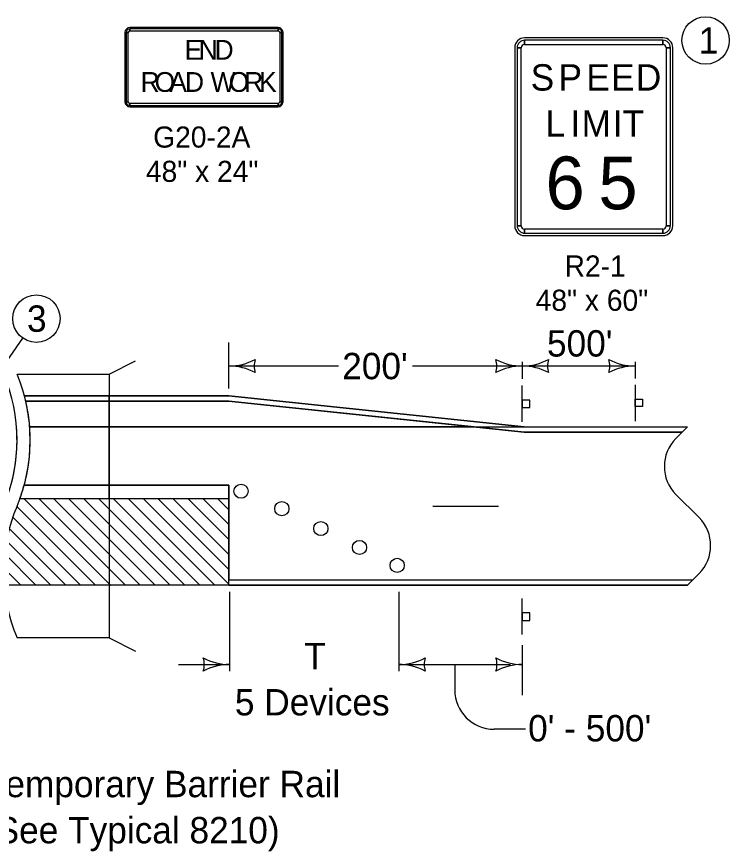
# Model space of a CAD drawing. Extents: x 10133 to 2270741, y 5363 to 1733450.
# Drawn here: x 30695 to 31236, y 11491 to 12124 of the extents above; entities that cross this region are included whole.
import ezdxf

# ---------------------------------------------------------------- set-up
doc = ezdxf.new("R2010")
doc.units = 0
for name, color, linetype in [('dsnNonPlotable', 7, 'Continuous'), ('dsnShtPlotShapeBatchPrint', 7, 'Continuous'), ('dsnStdBorder', 7, 'Continuous'), ('dsnStdLabel', 7, 'Continuous'), ('Level 12', 7, 'Continuous'), ('Level 2', 7, 'Continuous')]:
    doc.layers.add(name, color=color, linetype=linetype)

msp = doc.modelspace()

# ---------------------------------------------------------------- linework, layer by layer
at = {"layer": 'dsnNonPlotable'}
for p, q in [((30765.21, 11852.62), (30785.21, 11862.62)), ((30695.21, 11852.62), (30765.21, 11852.62)), ((30701.82, 11832.12), (30855.98, 11832.12)), ((30855.98, 11832.12), (31080.18, 11808.62)), ((30704.83, 11812.62), (31080.2, 11812.62)), ((31204.03, 11812.62), (31195.24, 11803.83)), ((30855.98, 11768.35), (30700.62, 11768.35)), ((30855.98, 11758.35), (30855.98, 11768.35)), ((31195.24, 11761.4), (31212.81, 11743.83)), ((30697.45, 11758.35), (30855.98, 11758.35)), ((31212.81, 11701.4), (31204.03, 11692.62)), ((30765.21, 11652.62), (30785.21, 11642.62))]:
    msp.add_line(p, q, dxfattribs=at)
for points in [[(30765.21, 11852.62), (30765.21, 11652.62), (30695.21, 11652.62)], [(31080.18, 11808.62), (31200.03, 11808.62)], [(30713.68, 11768.35), (30700.62, 11768.35)], [(30697.45, 11758.35), (30710.51, 11758.35)], [(31010.64, 11752.62), (31060.64, 11752.62)], [(30855.98, 11696.62), (31208.03, 11696.62)]]:
    msp.add_lwpolyline(points, dxfattribs=at)
for centre, radius, start, end in [((30565.21, 11802.62), 130, 337.38013, 22.61986), ((30575.21, 11802.62), 130, 337.38013, 22.61986), ((31216.46, 11782.62), 30, 135, 225), ((30815.21, 11702.62), 130, 157.38013, 202.61986), ((31191.6, 11722.62), 30, 315, 45)]:
    msp.add_arc(centre, radius, start, end, dxfattribs=at)
at = {"layer": 'dsnShtPlotShapeBatchPrint'}
for centre in [(31217.76, 12105.69), (30709.93, 11894.73)]:
    msp.add_circle(centre, 18, dxfattribs=at)
at = {"layer": 'dsnStdBorder'}
for p, q in [((30893.34, 12115.42), (30780.84, 12115.42)), ((30780.84, 12112.92), (30780.84, 12114.49)), ((30893.34, 12114.49), (30893.34, 12112.92)), ((30777.09, 12111.67), (30777.09, 12059.17)), ((30778.03, 12111.67), (30779.59, 12111.67)), ((30894.59, 12111.67), (30896.15, 12111.67)), ((30897.09, 12059.17), (30897.09, 12111.67)), ((31185.39, 12107.65), (31080.39, 12107.65)), ((31080.39, 12102.65), (31080.39, 12105.78)), ((31185.39, 12105.78), (31185.39, 12102.65)), ((31072.89, 12100.15), (31072.89, 11965.15)), ((31074.77, 12100.15), (31077.89, 12100.15)), ((31187.89, 12100.15), (31191.02, 12100.15)), ((31192.89, 11965.15), (31192.89, 12100.15)), ((30779.59, 12059.17), (30778.03, 12059.17)), ((30780.84, 12056.36), (30780.84, 12057.92)), ((30893.34, 12057.92), (30893.34, 12056.36)), ((30896.15, 12059.17), (30894.59, 12059.17)), ((30780.84, 12055.42), (30893.34, 12055.42)), ((31077.89, 11965.15), (31074.77, 11965.15)), ((31080.39, 11959.53), (31080.39, 11962.65)), ((31185.39, 11962.65), (31185.39, 11959.53)), ((31191.02, 11965.15), (31187.89, 11965.15)), ((31080.39, 11957.65), (31185.39, 11957.65)), ((31078.59, 11816.53), (31078.59, 11844.03)), ((31164.24, 11844.5), (31164.24, 11817)), ((30855.98, 11832.12), (31080.18, 11808.62)), ((31080.18, 11808.62), (31200.03, 11808.62)), ((30713.68, 11768.35), (30700.62, 11768.35)), ((30765.21, 11768.35), (30713.68, 11768.35)), ((30855.98, 11768.35), (30765.21, 11768.35)), ((30765.21, 11768.35), (30765.21, 11758.35)), ((30765.21, 11758.35), (30765.21, 11768.35)), ((30855.98, 11758.35), (30855.98, 11768.35)), ((30697.45, 11758.35), (30710.51, 11758.35)), ((30700.38, 11758.35), (30766.11, 11692.62)), ((30710.51, 11758.35), (30765.21, 11758.35)), ((30711.69, 11758.35), (30777.42, 11692.62)), ((30723, 11758.35), (30788.74, 11692.62)), ((30734.32, 11758.35), (30800.05, 11692.62)), ((30745.63, 11758.35), (30811.37, 11692.62)), ((30756.94, 11758.35), (30822.68, 11692.62)), ((30765.21, 11758.35), (30855.98, 11758.35)), ((30768.26, 11758.35), (30833.99, 11692.62)), ((30779.57, 11758.35), (30845.31, 11692.62)), ((30790.89, 11758.35), (30855.98, 11693.26)), ((30802.2, 11758.35), (30855.98, 11704.58)), ((30813.51, 11758.35), (30855.98, 11715.89)), ((30824.83, 11758.35), (30855.98, 11727.2)), ((30836.14, 11758.35), (30855.98, 11738.52)), ((30847.45, 11758.35), (30855.98, 11749.83)), ((30855.98, 11692.62), (30855.98, 11758.35)), ((30695.09, 11752.32), (30754.8, 11692.62)), ((30692.01, 11744.09), (30743.48, 11692.62)), ((30689.41, 11735.38), (30732.17, 11692.62)), ((30687.36, 11726.12), (30720.86, 11692.62)), ((30685.93, 11716.23), (30709.54, 11692.62)), ((30685.25, 11705.6), (30698.23, 11692.62)), ((30766.11, 11692.62), (30765.21, 11693.51)), ((30765.21, 11693.51), (30765.21, 11692.62)), ((30765.21, 11692.62), (30766.11, 11692.62)), ((31078.59, 11655.08), (31078.59, 11682.58))]:
    msp.add_line(p, q, dxfattribs=at)
for points in [[(30893.34, 12114.49), (30780.84, 12114.49), (30780.84, 12112.92), (30893.34, 12112.92), (30893.34, 12114.49)], [(30778.03, 12111.67), (30778.03, 12059.17), (30779.59, 12059.17), (30779.59, 12111.67), (30778.03, 12111.67)], [(30896.15, 12059.17), (30896.15, 12111.67), (30894.59, 12111.67), (30894.59, 12059.17), (30896.15, 12059.17)], [(31185.39, 12105.78), (31080.39, 12105.78), (31080.39, 12102.65), (31185.39, 12102.65), (31185.39, 12105.78)], [(31074.77, 12100.15), (31074.77, 11965.15), (31077.89, 11965.15), (31077.89, 12100.15), (31074.77, 12100.15)], [(31191.02, 11965.15), (31191.02, 12100.15), (31187.89, 12100.15), (31187.89, 11965.15), (31191.02, 11965.15)], [(30780.84, 12056.36), (30893.34, 12056.36), (30893.34, 12057.92), (30780.84, 12057.92), (30780.84, 12056.36)], [(31080.39, 11959.53), (31185.39, 11959.53), (31185.39, 11962.65), (31080.39, 11962.65), (31080.39, 11959.53)], [(31078.68, 11832.98), (31078.68, 11827.35), (31084.31, 11827.35), (31084.31, 11832.98)], [(31164.34, 11828.05), (31164.34, 11833.68), (31169.96, 11833.68), (31169.96, 11828.05)], [(31078.68, 11671.53), (31078.68, 11665.9), (31084.31, 11665.9), (31084.31, 11671.53)]]:
    msp.add_lwpolyline(points, close=True, dxfattribs=at)
for centre in [(30865.2, 11763.82), (30865.2, 11763.82), (30896.16, 11750.6), (30896.16, 11750.6), (30925.78, 11735.5), (30925.78, 11735.5), (30955.11, 11721.19), (30955.11, 11721.19), (30983.7, 11707.58), (30983.7, 11707.58)]:
    msp.add_circle(centre, 5.37, dxfattribs=at)
for centre, radius, start, end in [((30780.84, 12111.67), 3.75, 90.00021, 179.99985), ((30780.84, 12111.67), 2.81, 90.00021, 179.99985), ((30893.34, 12111.67), 3.75, 0, 90.00021), ((30893.34, 12111.67), 2.81, 0, 90.00021), ((30780.84, 12111.67), 1.25, 90.00021, 179.99985), ((30893.34, 12111.67), 1.25, 0, 90.00021), ((31080.39, 12100.15), 7.5, 90.00021, 179.99985), ((31080.39, 12100.15), 5.62, 90.00021, 179.99985), ((31080.39, 12100.15), 2.5, 90.00021, 179.99985), ((31185.39, 12100.15), 7.5, 0, 90.00021), ((31185.39, 12100.15), 5.62, 0, 90.00021), ((31185.39, 12100.15), 2.5, 0, 90.00021), ((30780.84, 12059.17), 3.75, 179.99985, 270.00006), ((30780.84, 12059.17), 2.81, 179.99985, 270.00006), ((30780.84, 12059.17), 1.25, 179.99985, 270.00006), ((30893.34, 12059.17), 3.75, 270.00006, 0.00027), ((30893.34, 12059.17), 2.81, 270.00006, 0.00027), ((30893.34, 12059.17), 1.25, 270.00006, 0.00027), ((31080.39, 11965.15), 7.5, 179.99985, 270.00006), ((31080.39, 11965.15), 5.62, 179.99985, 270.00006), ((31080.39, 11965.15), 2.5, 179.99985, 270.00006), ((31185.39, 11965.15), 7.5, 270.00006, 0.00027), ((31185.39, 11965.15), 5.62, 270.00006, 0.00027), ((31185.39, 11965.15), 2.5, 270.00006, 0.00027), ((30855.98, 11901.26), 42.5, 270, 298.07249), ((30891.61, 11858.76), 16.42, 162.26665, 197.73335), ((31042.95, 11858.76), 16.42, 342.26665, 17.73335), ((31078.59, 11901.26), 42.5, 241.92751, 270), ((31078.59, 11901.26), 42.5, 270, 298.07249), ((31114.22, 11858.76), 16.42, 162.26665, 197.73335), ((31128.6, 11858.76), 16.42, 342.26665, 17.73335), ((31164.24, 11901.26), 42.5, 241.92751, 270), ((30855.98, 11816.26), 42.5, 61.92751, 90), ((31078.59, 11816.26), 42.5, 90, 118.07249), ((31078.59, 11816.26), 42.5, 61.92751, 90), ((31164.24, 11816.26), 42.5, 90, 118.07249), ((30575.21, 11802.62), 130, 340.09183, 344.71678)]:
    msp.add_arc(centre, radius, start, end, dxfattribs=at)
at = {"layer": 'dsnStdLabel'}
for p, q in [((31078.59, 11862.07), (31078.59, 11849.12)), ((31164.24, 11862.07), (31164.24, 11849.39)), ((31164.24, 11858.76), (31078.59, 11858.76))]:
    msp.add_line(p, q, dxfattribs=at)
at = {"layer": 'Level 12'}
for p, q in [((30606.63, 11745.63), (30699.65, 11879.95)), ((30855.98, 11841.78), (30855.98, 11876.73)), ((30939.11, 11858.76), (30855.98, 11858.76)), ((31078.59, 11858.76), (30995.42, 11858.76)), ((30856.51, 11687.57), (30856.51, 11627.39)), ((30985, 11687.57), (30985, 11627.39)), ((31078.59, 11647.08), (31078.59, 11609.05)), ((30817.72, 11632.4), (30856.57, 11632.4)), ((30985, 11632.4), (31069.72, 11632.4)), ((31027.36, 11632.4), (31027.36, 11613.31)), ((31080.97, 11583.31), (31057.36, 11583.31))]:
    msp.add_line(p, q, dxfattribs=at)
for centre, radius, start, end in [((30820.93, 11632.4), 16.42, 342.26665, 17.73335), ((30856.57, 11674.9), 42.5, 241.92751, 270), ((30984.94, 11674.9), 42.5, 270, 298.07249), ((31020.58, 11632.4), 16.42, 162.26665, 197.73335), ((31043.02, 11632.4), 16.42, 342.26665, 17.73335), ((31078.66, 11674.9), 42.5, 241.92751, 270), ((30856.57, 11589.9), 42.5, 90, 118.07249), ((30984.94, 11589.9), 42.5, 61.92751, 90), ((31078.66, 11589.9), 42.5, 90, 118.07249), ((31057.36, 11613.31), 30, 180, 270)]:
    msp.add_arc(centre, radius, start, end, dxfattribs=at)
at = {"layer": 'Level 2'}
for p, q in [((30765.21, 11836.12), (30700.82, 11836.12)), ((30700.85, 11836.12), (30855.98, 11836.12)), ((30700.85, 11836.12), (30713.89, 11836.12)), ((30855.98, 11836.12), (30765.21, 11836.12)), ((30765.21, 11836.12), (30765.21, 11832.12)), ((30765.21, 11832.12), (30765.21, 11836.12)), ((30855.98, 11836.12), (31080.18, 11812.62)), ((31080.18, 11812.62), (30855.98, 11836.12)), ((30701.82, 11832.12), (30714.89, 11832.12)), ((30714.89, 11832.12), (30765.21, 11832.12)), ((30765.21, 11832.12), (30855.98, 11832.12)), ((30855.98, 11832.12), (30765.21, 11832.12)), ((30765.21, 11832.12), (30765.21, 11812.62)), ((30765.21, 11812.62), (30765.21, 11832.12)), ((30855.98, 11832.12), (31042.02, 11812.62)), ((31042.02, 11812.62), (30855.98, 11832.12)), ((30765.21, 11812.62), (30704.83, 11812.62)), ((30704.83, 11812.62), (30765.21, 11812.62)), ((30765.21, 11812.62), (30998.37, 11812.62)), ((30765.21, 11768.35), (30765.21, 11812.62)), ((30765.21, 11812.62), (30765.21, 11768.35)), ((30998.37, 11812.62), (31204.03, 11812.62)), ((30998.37, 11812.62), (31042.02, 11812.62)), ((31042.02, 11812.62), (31080.18, 11812.62)), ((31080.18, 11808.62), (31042.02, 11812.62)), ((31080.18, 11808.62), (31042.03, 11812.62)), ((31042.03, 11812.62), (31080.2, 11812.62)), ((31080.2, 11812.62), (31204.03, 11812.62)), ((31204.03, 11812.62), (31200.03, 11808.62)), ((31200.03, 11808.62), (31080.18, 11808.62)), ((31200.03, 11808.62), (31080.18, 11808.62)), ((31195.24, 11803.83), (31200.03, 11808.62)), ((30700.62, 11768.35), (30713.68, 11768.35)), ((30713.68, 11768.35), (30765.21, 11768.35)), ((30765.21, 11768.35), (30855.98, 11768.35)), ((30855.98, 11768.35), (30855.98, 11758.35)), ((31212.82, 11743.83), (31195.24, 11761.4)), ((30855.98, 11758.35), (30855.98, 11752.62)), ((30855.98, 11752.62), (30855.98, 11749.83)), ((30855.98, 11749.83), (30855.98, 11738.52)), ((30855.98, 11738.52), (30855.98, 11727.2)), ((30855.98, 11704.58), (30855.98, 11696.62)), ((30855.98, 11696.62), (31208.03, 11696.62)), ((30855.98, 11696.62), (31208.03, 11696.62)), ((31208.03, 11696.62), (31204.03, 11692.62)), ((31208.03, 11696.62), (31212.82, 11701.4)), ((30855.98, 11692.62), (30685.6, 11692.62)), ((31204.03, 11692.62), (30855.98, 11692.62)), ((30855.98, 11692.62), (31204.03, 11692.62))]:
    msp.add_line(p, q, dxfattribs=at)
for points in [[(30765.21, 11832.12), (30714.89, 11832.12), (30701.82, 11832.12)], [(31042.02, 11812.62), (30998.37, 11812.62), (30765.21, 11812.62)], [(30998.37, 11812.62), (30998.37, 11812.62)], [(31080.2, 11812.62), (31080.2, 11812.62)], [(31200.03, 11808.62), (31200.03, 11808.62)], [(31200.03, 11808.62), (31200.03, 11808.62)], [(30855.98, 11727.2), (30855.98, 11715.89), (30855.98, 11704.58)], [(30855.98, 11692.62), (30855.98, 11693.26), (30855.98, 11696.62)], [(31208.03, 11696.62), (31208.03, 11696.62)], [(31208.03, 11696.62), (31208.03, 11696.62)]]:
    msp.add_lwpolyline(points, dxfattribs=at)
for centre, radius, start, end in [((30575.21, 11802.62), 130, 13.11745, 14.93465), ((30575.21, 11802.62), 130, 4.41084, 13.11745), ((30565.21, 11802.62), 130, 344.71769, 4.41173), ((30575.21, 11802.62), 130, 344.71678, 4.41084), ((31216.46, 11782.62), 30, 135, 225), ((31191.6, 11722.62), 30, 315, 45)]:
    msp.add_arc(centre, radius, start, end, dxfattribs=at)

# ---------------------------------------------------------------- texts
at = {"layer": 'dsnShtPlotShapeBatchPrint'}
for s, p in [('1', (31212.56, 12095.69)), ('3', (30702.79, 11884.73))]:
    msp.add_text(s, height=20, dxfattribs=at).set_placement(p)
at = {"layer": 'dsnStdBorder'}
for s, height, p in [('E', 15, (30822.42, 12091.05)), ('N', 15, (30833.04, 12091.05)), ('D', 15, (30845.12, 12091.05)), ('S', 20, (31085.02, 12067.65)), ('P', 20, (31106.11, 12067.65)), ('E', 20, (31127.21, 12067.65)), ('E', 20, (31146.02, 12067.65)), ('D', 20, (31164.82, 12067.65)), ('R', 15, (30788.95, 12066.67)), ('O', 15, (30799.64, 12066.67)), ('A', 15, (30810.79, 12066.67)), ('D', 15, (30822.65, 12066.67)), ('W', 15, (30842.1, 12066.67)), ('O', 15, (30855.84, 12066.67)), ('R', 15, (30867.6, 12066.67)), ('K', 15, (30878.9, 12066.67)), ('L', 20, (31096.27, 12032.65)), ('I', 20, (31115.08, 12032.65)), ('M', 20, (31123.67, 12032.65)), ('I', 20, (31147.27, 12032.65)), ('T', 20, (31154.82, 12032.65)), ('G20-2A', 16, (30798.56, 12024.42)), ('48" x 24"', 16, (30793.02, 11998.42)), ('6', 40, (31096.27, 11977.65)), ('5', 40, (31136.39, 11977.65)), ('R2-1', 16, (31110.73, 11926.65)), ('48" x 60"', 16, (31088.82, 11900.65))]:
    msp.add_text(s, height=height, dxfattribs=at).set_placement(p)
at = {"layer": 'dsnStdLabel'}
for s, p in [("500'", (31097.38, 11865.94)), ("200'", (30941.97, 11848.76))]:
    msp.add_text(s, height=20, dxfattribs=at).set_placement(p)
at = {"layer": 'Level 12'}
for s, p in [('T', (30913.09, 11628.83)), ('5 Devices', (30860.54, 11593.83)), ("0' - 500'", (31083.07, 11574.11)), ('Temporary Barrier Rail', (30670.05, 11531.8)), ('(See Typical 8210)', (30670.05, 11496.8))]:
    msp.add_text(s, height=20, dxfattribs=at).set_placement(p)

doc.saveas('drawing.dxf')
